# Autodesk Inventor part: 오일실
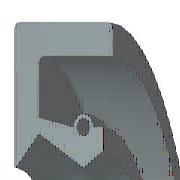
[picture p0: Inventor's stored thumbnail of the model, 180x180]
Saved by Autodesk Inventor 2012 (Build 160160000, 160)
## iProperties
IsCustomPart: 0
Company: 한국ATC센터
Created: 2014-10
Part Number: 오일실
Material: 고무
Description: 오일-실
Document SubType Name: Modeling
Standard: KS B 2804
Designer: KYOUNG IL JANG
Standards Organization: KS
Language: ko-KR
Size Designation: D - 17 32 8
Categories: <MemberInstance><Categories><Category DisplayName="샤프트 부품" InternalName="7f7aeb1f-a693-4053-b835-cee3144e0d98" Mnemonic="SHFT"><Category DisplayName="실링" Intern
Density: 0.93 g/cm^3
Mass: 2.28027 g
Surface Area: 32.1224 cm^2
Volume: 2.45191 cm^3
Author: KYOUNG IL JANG
Revision Number: 1
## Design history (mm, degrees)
revolve "본체" stored, may be unused: angle "d17" = 90 deg
revolve "스프링1" stored, may be unused: angle "d18" = 90 deg
body "Solid1"
sketch "스케치1"
  geometry: L1 (0, 16)-(8, 16); L2 (8, 14.25)-(1.75, 14.25); L3 (1.75, 10.25)-(4.9, 8.5); L4 (4.9, 8.5)-(0, 8.5); L5 (0, 0)-(9.586, 0) reference; L6 (4.9, 8.5)-(6.3, 9.375); L7 (0, 18)-(0, -3) reference; L8 (-1.941, 0)-(11.507, 0) reference; L9 (4.2, 10.6)-(1.75, 11.21); L10 (1.75, 11.21)-(1.75, 14.25); L11 (0, 16)-(0, 8.588); L12 (4.9, 8.5)-(0, 8.5); L13 (1.75, 10.25)-(0.152, 8.528); L14 (8, 16)-(8, 14.25); L15 (5.6, 10.6)-(6.3, 10.6); L16 (6.3, 10.6)-(6.3, 9.375); C1 r 0.455 at (4.9, 10.6); A1 r 0.7 centre (4.9, 10.6) between (5.6, 10.6) and (4.2, 10.6); A2 r 0.088 centre (0.088, 8.588) between (0, 8.588) and (0.152, 8.528); 1 further point
  constraints: 28 end point, 5 horizontal alignment, 5 point on line, 4 point on circle, 4 vertical alignment, 3 centre point, 3 tangent, 2 collinear, 2 horizontal, 2 perpendicular, 1 coincident, 1 parallel
  dimensions: "d0" = 32 diameter of L1 L5 (= SD2); "d1" = 1.75 distance of L1.end L2.start (= SD); "d2" = 0.91 diameter of C1 (= SPDI); "d3" = 1.4 diameter of A1 (= SPDA); "d4" = 17 diameter of L3.end L5 (= NND); "d5" = 20.5 diameter of L3.start L5 (= TKDM); "d7" = 22.42 diameter of L9.end L5 (= TKDM + 0.24 x SWDT); "d8" = 1.75 distance between parallel lines of L11 L10 (= SD); "d9" = 4.9 distance from line of L11 C1.centre (= SPDST); "d10" = 21.2 diameter of C1.centre L5 (= HLDM); "d11" = 0.0875 radius of A2 (= 0.25 x LAB); "d12" = 6.3 distance between parallel lines of L11 L16 (= SDI); "d13" = 18.75 diameter of L6.end L5 (= ABDM); "d14" = 8 distance from line of L11 L1.end (= SWDT)
fillet "모깎기1" dims "d6" = 0.3 (= RR)
other parameters: "SD2" = 32 [user parameter; used in 1 equation term], "SWDT" = 8 [user parameter; used in 2 equation terms], "RR" = 0.3 [user parameter; used in 1 equation term], "SD" = 1.75 [user parameter; used in 2 equation terms], "NND" = 17 [user parameter; used in 1 equation term], "SPDA" = 1.4 [user parameter; used in 1 equation term], "SPDI" = 0.91 [user parameter; used in 1 equation term], "TKDM" = 20.5 [user parameter; used in 2 equation terms], "HLDM" = 21.2 [user parameter; used in 1 equation term], "ABDM" = 18.75 [user parameter; used in 1 equation term], "SDI" = 6.3 [user parameter; used in 1 equation term], "SPDST" = 4.9 [user parameter; used in 1 equation term], "LAB" = 0.35 [user parameter; used in 1 equation term], "d15" = 0, "d16" = 0, "d19" = 0
